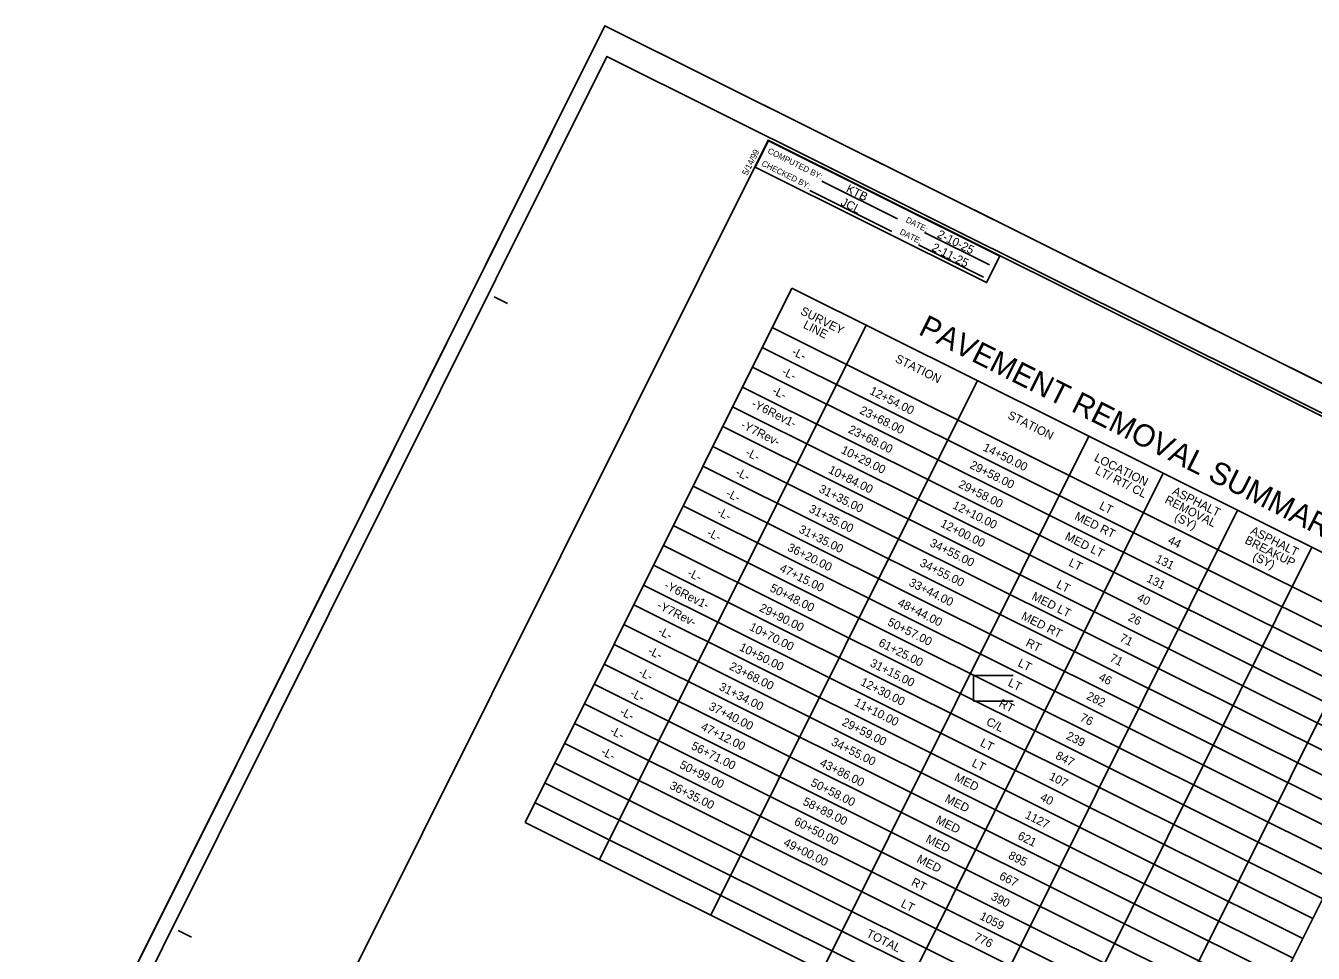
# Model space of a CAD drawing. Extents: x 1771109 to 1774678, y 884436 to 887277.
# Drawn here: x 1772681 to 1773772, y 886491 to 887277 of the extents above; entities that cross this region are included whole.
import ezdxf

# ---------------------------------------------------------------- set-up
doc = ezdxf.new("R2010")
doc.units = 0
for name, color, linetype in [('Sheet Block Check By Box CELL', 7, 'Continuous'), ('Sheet Border Standard 30in CELL', 7, 'Continuous'), ('Sheet Cutting Line CELL', 7, 'Continuous'), ('Sheet Plot Border Inside CELL', 7, 'Continuous'), ('Sheet Plot Border Outside CELL', 7, 'Continuous'), ('Sheet Summary Combination CELL', 7, 'Continuous'), ('Sheet Summary Combination Grid CELL', 7, 'Continuous')]:
    doc.layers.add(name, color=color, linetype=linetype)

msp = doc.modelspace()

# ---------------------------------------------------------------- linework, layer by layer
at = {"layer": 'Sheet Block Check By Box CELL'}
for p, q in [((1773355.2, 887145.4), (1773419.2, 887113.5)), ((1773345.1, 887137.4), (1773414.6, 887102.7)), ((1773442.2, 887101.8), (1773497.2, 887074.4)), ((1773437.2, 887091.5), (1773492.2, 887064.1))]:
    msp.add_line(p, q, dxfattribs=at)
msp.add_lwpolyline([(1773310, 887179.5), (1773506, 887081.8), (1773494.8, 887059.4), (1773298.8, 887157.2)], close=True, dxfattribs=at)
at = {"layer": 'Sheet Border Standard 30in CELL'}
for p, q in [((1773310.6, 887179.8), (1773310.6, 887179.8)), ((1773077.6, 887047.4), (1773088.7, 887041.8)), ((1772809.8, 886510.4), (1772821, 886504.8))]:
    msp.add_line(p, q, dxfattribs=at)
msp.add_lwpolyline([(1774652.1, 886510.9), (1773309.7, 887180.2), (1772841.2, 886240.6), (1774183.6, 885571.2)], close=True, dxfattribs=at)
at = {"layer": 'Sheet Cutting Line CELL'}
for p, q in [((1773171.4, 887277.1), (1772680.6, 886292.7)), ((1774678.5, 886525.7), (1773171.4, 887277.1)), ((1773517.3, 886726.5), (1773483.6, 886726.5)), ((1773483.6, 886726.5), (1773483.6, 886704.6)), ((1773483.6, 886704.6), (1773517.3, 886704.6))]:
    msp.add_line(p, q, dxfattribs=at)
at = {"layer": 'Sheet Plot Border Inside CELL'}
msp.add_lwpolyline([(1774664.4, 886507.6), (1773173, 887251.2), (1772702.3, 886307), (1774193.7, 885563.4)], close=True, dxfattribs=at)
at = {"layer": 'Sheet Plot Border Outside CELL'}
msp.add_lwpolyline([(1774678.5, 886525.7), (1773171.4, 887277.1), (1772680.6, 886292.7), (1774187.7, 885541.3)], close=True, dxfattribs=at)
at = {"layer": 'Sheet Summary Combination CELL'}
for p, q in [((1773519.3, 886960.2), (1773519.3, 886960.2)), ((1773527.6, 886955.9), (1773527.6, 886955.9)), ((1773539.9, 886950.1), (1773539.9, 886950.1)), ((1773547.4, 886946.2), (1773547.4, 886946.2))]:
    msp.add_line(p, q, dxfattribs=at)
at = {"layer": 'Sheet Summary Combination Grid CELL'}
for p, q in [((1773329.7, 887054.8), (1773103.8, 886601.8)), ((1773329.7, 887054.8), (1773896.7, 886772.2)), ((1773392.7, 887023.4), (1773166.8, 886570.4)), ((1773313, 887021.3), (1773880, 886738.6)), ((1773304.6, 887004.5), (1773871.6, 886721.8)), ((1773296.3, 886987.7), (1773863.2, 886705)), ((1773487.1, 886976.4), (1773261.2, 886523.3)), ((1773287.9, 886970.9), (1773854.9, 886688.3)), ((1773279.5, 886954.2), (1773846.5, 886671.5)), ((1773271.2, 886937.4), (1773838.1, 886654.7)), ((1773581.5, 886929.3), (1773355.6, 886476.2)), ((1773262.8, 886920.6), (1773829.8, 886637.9)), ((1773254.4, 886903.8), (1773821.4, 886621.1)), ((1773644.5, 886897.9), (1773418.6, 886444.9)), ((1773246.1, 886887), (1773813, 886604.4)), ((1773237.7, 886870.3), (1773804.7, 886587.6)), ((1773707.4, 886866.5), (1773481.5, 886413.5)), ((1773229.3, 886853.5), (1773796.3, 886570.8)), ((1773221, 886836.7), (1773787.9, 886554)), ((1773770.5, 886835.1), (1773544.6, 886382)), ((1773212.6, 886819.9), (1773779.6, 886537.2)), ((1773204.2, 886803.1), (1773771.2, 886520.5)), ((1773833.6, 886803.6), (1773607.7, 886350.6)), ((1773195.9, 886786.4), (1773762.8, 886503.7)), ((1773187.5, 886769.6), (1773754.5, 886486.9)), ((1773896.7, 886772.2), (1773670.8, 886319.1)), ((1773179.1, 886752.8), (1773746.1, 886470.1)), ((1773170.8, 886736), (1773737.7, 886453.3)), ((1773162.4, 886719.2), (1773729.4, 886436.6)), ((1773154, 886702.5), (1773721, 886419.8)), ((1773145.7, 886685.7), (1773712.6, 886403)), ((1773137.3, 886668.9), (1773704.3, 886386.2)), ((1773128.9, 886652.1), (1773695.9, 886369.4)), ((1773120.6, 886635.3), (1773687.5, 886352.7)), ((1773112.2, 886618.6), (1773679.2, 886335.9)), ((1773103.8, 886601.8), (1773670.8, 886319.1))]:
    msp.add_line(p, q, dxfattribs=at)

# ---------------------------------------------------------------- texts
at = {"layer": 'Sheet Block Check By Box CELL'}
for s, p in [('COMPUTED BY:', (1773308.8, 887169.4)), ('CHECKED BY:', (1773303.6, 887158.8)), ('DATE:', (1773425.8, 887110.9)), ('DATE:', (1773420.7, 887100.7))]:
    msp.add_text(s, height=5, rotation=333.4993, dxfattribs=at).set_placement(p)
at = {"layer": 'Sheet Border Standard 30in CELL'}
msp.add_text('5/14/99', height=5.25, rotation=63.4993, dxfattribs=at).set_placement((1773292, 887149.7))
at = {"layer": 'Sheet Summary Combination CELL'}
for s, height, rotation, p in [('KTB', 7.2, 333.3081, (1773375.1, 887136.6)), ('JCL', 7.2, 333.3081, (1773370.6, 887125.4)), ('2-10-25', 7.2, 333.3081, (1773452.3, 887098.1)), ('2-11-25', 7.2, 333.3081, (1773447.7, 887087)), ('SURVEY', 7.2, 333.3081, (1773336.4, 887033)), ('PAVEMENT REMOVAL SUMMARY', 18.75, 333.3201, (1773436.1, 887016)), ('LINE', 7.2, 333.3081, (1773338.8, 887021.3)), ('-L- ', 7.2, 333.3081, (1773329.1, 886998.7)), ('STATION', 7.2, 333.3081, (1773416.7, 886992.6)), ('-L-', 7.2, 333.3081, (1773320.7, 886981.8)), ('-L-', 7.2, 333.3081, (1773312.5, 886965.6)), ('12+54.00', 7.2, 333.3081, (1773395, 886965.4)), ('-Y6Rev1-', 7.2, 333.3081, (1773295, 886954.6)), ('23+68.00', 7.2, 333.3081, (1773386.6, 886948.9)), ('STATION', 7.2, 333.3081, (1773512, 886944.7)), ('-Y7Rev-', 7.2, 333.3081, (1773285.9, 886936.6)), ('23+68.00', 7.2, 333.3081, (1773376.9, 886932.7)), ('14+50.00', 7.2, 333.3081, (1773491.1, 886917.5)), ('-L-', 7.2, 333.3081, (1773289.9, 886913.3)), ('10+29.00', 7.2, 333.3081, (1773370.8, 886915.3)), ('LOCATION', 7.2, 333.3081, (1773585.4, 886908.8)), ('-L-', 7.2, 333.3081, (1773281.5, 886896.4)), ('10+84.00', 7.2, 333.3081, (1773360.1, 886898.6)), ('29+58.00', 7.2, 333.3081, (1773479.9, 886902.6)), ('LT/ RT/ CL', 7.2, 333.3081, (1773586.2, 886897.9)), ('29+58.00', 7.2, 333.3081, (1773470.3, 886886.3)), ('-L-', 7.2, 333.3081, (1773273.4, 886878.6)), ('31+35.00', 7.2, 333.3081, (1773352, 886882.3)), ('REMOVAL', 7.2, 333.3081, (1773645.1, 886873.1)), ('ASPHALT', 7.2, 333.3081, (1773651.5, 886880.5)), ('-L-', 7.2, 333.3081, (1773265.6, 886862.9)), ('31+35.00', 7.2, 333.3081, (1773343.6, 886865.4)), ('12+10.00', 7.2, 333.3081, (1773465.3, 886868.5)), ('LT', 7.2, 333.3081, (1773589.7, 886868.1)), ('12+00.00', 7.2, 333.3081, (1773455.1, 886853)), ('MED RT', 7.2, 333.3081, (1773568.7, 886859.2)), ('(SY)', 7.2, 333.3081, (1773653.3, 886858.4)), ('-L-', 7.2, 333.3081, (1773257.2, 886845.2)), ('31+35.00', 7.2, 333.3081, (1773335, 886848.1)), ('MED LT', 7.2, 333.3081, (1773560.6, 886842)), ('ASPHALT', 7.2, 333.3081, (1773717.7, 886847)), ('36+20.00', 7.2, 333.3081, (1773325.4, 886832.7)), ('34+55.00', 7.2, 333.3081, (1773446, 886836.5)), ('44', 7.2, 333.3081, (1773647.8, 886838.9)), ('BREAKUP', 7.2, 333.3081, (1773712.9, 886838.9)), ('34+55.00', 7.2, 333.3081, (1773437.5, 886819.6)), ('LT', 7.2, 333.3081, (1773563.7, 886819.9)), ('131', 7.2, 333.3081, (1773637.2, 886823.1)), ('(SY)', 7.2, 333.3081, (1773719.6, 886825)), ('-L-', 7.2, 333.3081, (1773240.7, 886811.2)), ('47+15.00', 7.2, 333.3081, (1773318.7, 886815.1)), ('-Y6Rev1-', 7.2, 333.3081, (1773221, 886800.7)), ('50+48.00', 7.2, 333.3081, (1773310.5, 886798.3)), ('33+44.00', 7.2, 333.3081, (1773428.3, 886803)), ('LT', 7.2, 333.3081, (1773553.3, 886801.4)), ('131', 7.2, 333.3081, (1773629.7, 886806.4)), ('MED LT', 7.2, 333.3081, (1773532.4, 886791.3)), ('40', 7.2, 333.3081, (1773621.6, 886790.3)), ('-Y7Rev-', 7.2, 333.3081, (1773214.9, 886783.7)), ('29+90.00', 7.2, 333.3081, (1773301.6, 886781.5)), ('48+44.00', 7.2, 333.3081, (1773418.8, 886785.9)), ('MED RT', 7.2, 333.3081, (1773523.6, 886774.6)), ('10+70.00', 7.2, 333.3081, (1773293.1, 886765.3)), ('50+57.00', 7.2, 333.3081, (1773410.2, 886769.5)), ('26', 7.2, 333.3081, (1773614.1, 886773.5)), ('-L-', 7.2, 333.3081, (1773215.7, 886761.9)), ('71', 7.2, 333.3081, (1773606.9, 886756)), ('-L-', 7.2, 333.3081, (1773207.3, 886745.2)), ('10+50.00', 7.2, 333.3081, (1773284.6, 886748.2)), ('61+25.00', 7.2, 333.3081, (1773402.6, 886751.9)), ('RT', 7.2, 333.3081, (1773527.4, 886751.9)), ('23+68.00', 7.2, 333.3081, (1773276.1, 886732)), ('31+15.00', 7.2, 333.3081, (1773395.4, 886734.7)), ('LT', 7.2, 333.3081, (1773520.7, 886734.8)), ('71', 7.2, 333.3081, (1773598.5, 886739.1)), ('-L-', 7.2, 333.3081, (1773199.2, 886727)), ('46', 7.2, 333.3081, (1773589.1, 886722.9)), ('31+34.00', 7.2, 333.3081, (1773267.4, 886714.6)), ('12+30.00', 7.2, 333.3081, (1773387.2, 886718.7)), ('LT', 7.2, 333.3081, (1773512.3, 886718.1)), ('-L-', 7.2, 333.3081, (1773192.1, 886709.2)), ('11+10.00', 7.2, 333.3081, (1773381.9, 886701.4)), ('RT', 7.2, 333.3081, (1773504.5, 886700.6)), ('282', 7.2, 333.3081, (1773578.8, 886706.8)), ('-L-', 7.2, 333.3081, (1773183.4, 886693.6)), ('37+40.00', 7.2, 333.3081, (1773258.7, 886698)), ('76', 7.2, 333.3081, (1773573.3, 886688.5)), ('-L-', 7.2, 333.3081, (1773174.9, 886677.4)), ('47+12.00', 7.2, 333.3081, (1773252, 886680.8)), ('29+59.00', 7.2, 333.3081, (1773371.6, 886684.7)), ('C/L', 7.2, 333.3081, (1773493.8, 886685)), ('34+55.00', 7.2, 333.3081, (1773362.5, 886667.9)), ('LT', 7.2, 333.3081, (1773488.7, 886667.1)), ('239', 7.2, 333.3081, (1773561.6, 886673)), ('-L-', 7.2, 333.3081, (1773167.5, 886659.7)), ('56+71.00', 7.2, 333.3081, (1773243.8, 886664.5)), ('847', 7.2, 333.3081, (1773552.6, 886656.3)), ('50+99.00', 7.2, 333.3081, (1773234, 886648.5)), ('43+86.00', 7.2, 333.3081, (1773352.8, 886650.2)), ('LT', 7.2, 333.3081, (1773481.6, 886649.9)), ('50+58.00', 7.2, 333.3081, (1773345.1, 886633.4)), ('MED', 7.2, 333.3081, (1773466.8, 886637.8)), ('107', 7.2, 333.3081, (1773547.1, 886638.7)), ('36+35.00', 7.2, 333.3081, (1773225.6, 886630.9)), ('58+89.00', 7.2, 333.3081, (1773338.4, 886617.3)), ('MED', 7.2, 333.3081, (1773458.8, 886619.8)), ('40', 7.2, 333.3081, (1773539.5, 886621)), ('60+50.00', 7.2, 333.3081, (1773331, 886600.5)), ('MED', 7.2, 333.3081, (1773451.1, 886601.9)), ('1127', 7.2, 333.3081, (1773526.7, 886606)), ('49+00.00', 7.2, 333.3081, (1773322.1, 886582.7)), ('MED', 7.2, 333.3081, (1773442.6, 886585.7)), ('621', 7.2, 333.3081, (1773520.5, 886588.3)), ('MED', 7.2, 333.3081, (1773435, 886568.7)), ('895', 7.2, 333.3081, (1773512.6, 886571.7)), ('RT', 7.2, 333.3081, (1773430.3, 886549.1)), ('667', 7.2, 333.3081, (1773504.9, 886554.2)), ('390', 7.2, 333.3081, (1773497.8, 886536.9)), ('LT', 7.2, 333.3081, (1773421.5, 886530.8)), ('1059', 7.2, 333.3081, (1773488.3, 886520.3)), ('TOTAL', 7.2, 333.3081, (1773392.2, 886505.5)), ('776', 7.2, 333.3081, (1773483.5, 886502.7))]:
    msp.add_text(s, height=height, rotation=rotation, dxfattribs=at).set_placement(p)

doc.saveas('drawing.dxf')
